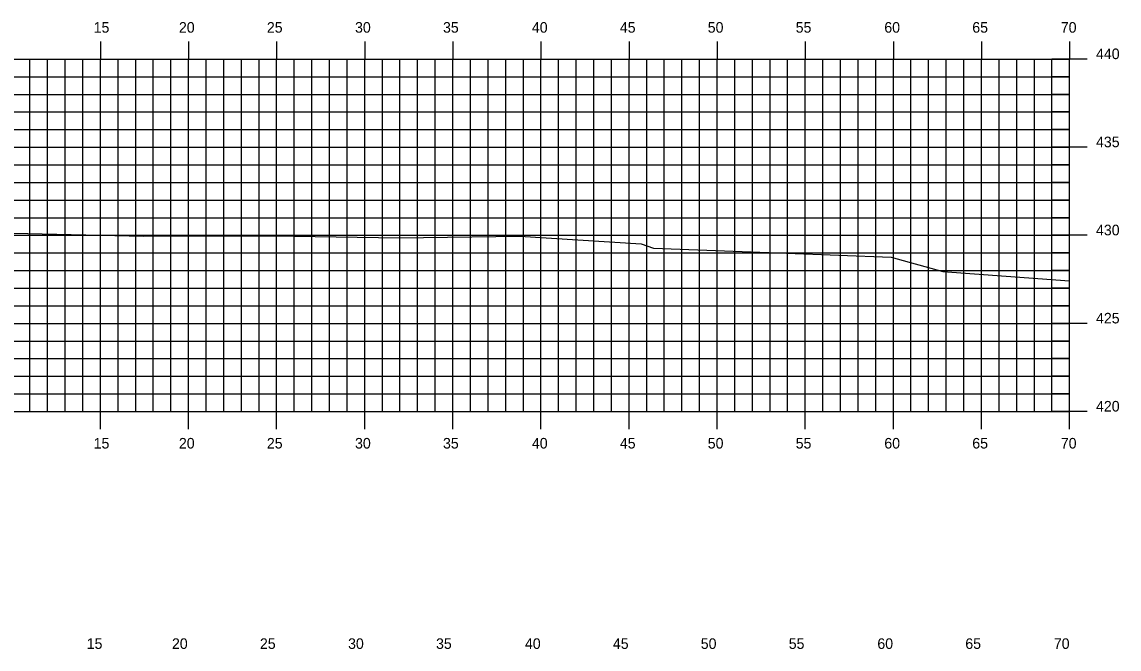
# Model space of a CAD drawing. Extents: x -161 to 764, y 111 to 210.
# Drawn here: x 165.1 to 227.4, y 153.7 to 189.3 of the extents above; entities that cross this region are included whole.
import ezdxf

# ---------------------------------------------------------------- set-up
doc = ezdxf.new("R2010")
doc.units = 0
for name, color, linetype in [('H_V ANNOTATION', 7, 'Continuous'), ('MAJOR', 7, 'Continuous'), ('MINOR', 7, 'Continuous'), ('S_Roadway_Centerline', 7, 'Continuous')]:
    doc.layers.add(name, color=color, linetype=linetype)

msp = doc.modelspace()

# ---------------------------------------------------------------- linework, layer by layer
at = {"layer": 'MAJOR'}
for p, q in [((169.563, 188.143), (169.563, 187.141)), ((174.563, 188.143), (174.563, 187.141)), ((179.563, 188.143), (179.563, 187.141)), ((184.563, 188.143), (184.563, 187.141)), ((189.563, 188.143), (189.563, 187.141)), ((194.563, 188.143), (194.563, 187.141)), ((199.563, 188.143), (199.563, 187.141)), ((204.563, 188.143), (204.563, 187.141)), ((209.563, 188.143), (209.563, 187.141)), ((214.563, 188.143), (214.563, 187.141)), ((219.563, 188.143), (219.563, 187.141)), ((224.563, 188.143), (224.563, 187.141)), ((84.563, 187.141), (224.563, 187.141)), ((84.563, 187.141), (224.563, 187.141)), ((169.563, 167.141), (169.563, 187.141)), ((174.563, 167.141), (174.563, 187.141)), ((179.563, 167.141), (179.563, 187.141)), ((184.563, 167.141), (184.563, 187.141)), ((189.563, 167.141), (189.563, 187.141)), ((194.563, 167.141), (194.563, 187.141)), ((199.563, 167.141), (199.563, 187.141)), ((204.563, 167.141), (204.563, 187.141)), ((209.563, 167.141), (209.563, 187.141)), ((214.563, 167.141), (214.563, 187.141)), ((219.563, 167.141), (219.563, 187.141)), ((225.565, 187.141), (223.561, 187.141)), ((224.563, 167.141), (224.563, 187.141)), ((224.563, 167.141), (224.563, 187.141)), ((84.563, 182.141), (224.563, 182.141)), ((225.565, 182.141), (223.561, 182.141)), ((84.563, 177.141), (224.563, 177.141)), ((225.565, 177.141), (223.561, 177.141)), ((84.563, 172.141), (224.563, 172.141)), ((225.565, 172.141), (223.561, 172.141)), ((84.563, 167.141), (224.563, 167.141)), ((84.563, 167.141), (224.563, 167.141)), ((169.563, 166.139), (169.563, 167.141)), ((174.563, 166.139), (174.563, 167.141)), ((179.563, 166.139), (179.563, 167.141)), ((184.563, 166.139), (184.563, 167.141)), ((189.563, 166.139), (189.563, 167.141)), ((194.563, 166.139), (194.563, 167.141)), ((199.563, 166.139), (199.563, 167.141)), ((204.563, 166.139), (204.563, 167.141)), ((209.563, 166.139), (209.563, 167.141)), ((214.563, 166.139), (214.563, 167.141)), ((219.563, 166.139), (219.563, 167.141)), ((225.565, 167.141), (223.561, 167.141)), ((224.563, 166.139), (224.563, 167.141))]:
    msp.add_line(p, q, dxfattribs=at)
at = {"layer": 'MINOR'}
for p, q in [((165.563, 167.141), (165.563, 187.141)), ((166.563, 167.141), (166.563, 187.141)), ((167.563, 167.141), (167.563, 187.141)), ((168.563, 167.141), (168.563, 187.141)), ((170.563, 167.141), (170.563, 187.141)), ((171.563, 167.141), (171.563, 187.141)), ((172.563, 167.141), (172.563, 187.141)), ((173.563, 167.141), (173.563, 187.141)), ((175.563, 167.141), (175.563, 187.141)), ((176.563, 167.141), (176.563, 187.141)), ((177.563, 167.141), (177.563, 187.141)), ((178.563, 167.141), (178.563, 187.141)), ((180.563, 167.141), (180.563, 187.141)), ((181.563, 167.141), (181.563, 187.141)), ((182.563, 167.141), (182.563, 187.141)), ((183.563, 167.141), (183.563, 187.141)), ((185.563, 167.141), (185.563, 187.141)), ((186.563, 167.141), (186.563, 187.141)), ((187.563, 167.141), (187.563, 187.141)), ((188.563, 167.141), (188.563, 187.141)), ((190.563, 167.141), (190.563, 187.141)), ((191.563, 167.141), (191.563, 187.141)), ((192.563, 167.141), (192.563, 187.141)), ((193.563, 167.141), (193.563, 187.141)), ((195.563, 167.141), (195.563, 187.141)), ((196.563, 167.141), (196.563, 187.141)), ((197.563, 167.141), (197.563, 187.141)), ((198.563, 167.141), (198.563, 187.141)), ((200.563, 167.141), (200.563, 187.141)), ((201.563, 167.141), (201.563, 187.141)), ((202.563, 167.141), (202.563, 187.141)), ((203.563, 167.141), (203.563, 187.141)), ((205.563, 167.141), (205.563, 187.141)), ((206.563, 167.141), (206.563, 187.141)), ((207.563, 167.141), (207.563, 187.141)), ((208.563, 167.141), (208.563, 187.141)), ((210.563, 167.141), (210.563, 187.141)), ((211.563, 167.141), (211.563, 187.141)), ((212.563, 167.141), (212.563, 187.141)), ((213.563, 167.141), (213.563, 187.141)), ((215.563, 167.141), (215.563, 187.141)), ((216.563, 167.141), (216.563, 187.141)), ((217.563, 167.141), (217.563, 187.141)), ((218.563, 167.141), (218.563, 187.141)), ((220.563, 167.141), (220.563, 187.141)), ((221.563, 167.141), (221.563, 187.141)), ((222.563, 167.141), (222.563, 187.141)), ((223.563, 167.141), (223.563, 187.141)), ((84.563, 186.141), (224.563, 186.141)), ((224.563, 186.141), (223.561, 186.141)), ((84.563, 185.141), (224.563, 185.141)), ((224.563, 185.141), (223.561, 185.141)), ((84.563, 184.141), (224.563, 184.141)), ((224.563, 184.141), (223.561, 184.141)), ((84.563, 183.141), (224.563, 183.141)), ((224.563, 183.141), (223.561, 183.141)), ((84.563, 181.141), (224.563, 181.141)), ((224.563, 181.141), (223.561, 181.141)), ((84.563, 180.141), (224.563, 180.141)), ((224.563, 180.141), (223.561, 180.141)), ((84.563, 179.141), (224.563, 179.141)), ((224.563, 179.141), (223.561, 179.141)), ((84.563, 178.141), (224.563, 178.141)), ((224.563, 178.141), (223.561, 178.141)), ((84.563, 176.141), (224.563, 176.141)), ((224.563, 176.141), (223.561, 176.141)), ((84.563, 175.141), (224.563, 175.141)), ((224.563, 175.141), (223.561, 175.141)), ((84.563, 174.141), (224.563, 174.141)), ((224.563, 174.141), (223.561, 174.141)), ((84.563, 173.141), (224.563, 173.141)), ((224.563, 173.141), (223.561, 173.141)), ((84.563, 171.141), (224.563, 171.141)), ((224.563, 171.141), (223.561, 171.141)), ((84.563, 170.141), (224.563, 170.141)), ((224.563, 170.141), (223.561, 170.141)), ((84.563, 169.141), (224.563, 169.141)), ((224.563, 169.141), (223.561, 169.141)), ((84.563, 168.141), (224.563, 168.141)), ((224.563, 168.141), (223.561, 168.141))]:
    msp.add_line(p, q, dxfattribs=at)
at = {"layer": 'S_Roadway_Centerline'}
msp.add_lwpolyline([(84.563, 173.937), (86.565, 173.962), (104.807, 174.158), (105.264, 174.178), (106.296, 174.117), (107.265, 173.972), (107.828, 174.003), (110.477, 174.125), (125.033, 175.141), (130.13, 175.365), (150.707, 176.49), (164.616, 177.272), (172.022, 177.096), (179.352, 177.108), (186.535, 177.007), (193.367, 177.096), (200.259, 176.65), (200.943, 176.413), (208.506, 176.123), (214.429, 175.907), (217.362, 175.08), (224.563, 174.564)], dxfattribs=at)

# ---------------------------------------------------------------- texts
at = {"layer": 'H_V ANNOTATION'}
for s, p in [('15', (169.18, 188.641)), ('20', (174.017, 188.641)), ('25', (179.009, 188.641)), ('30', (184.012, 188.641)), ('35', (189.004, 188.641)), ('40', (194.049, 188.641)), ('45', (199.041, 188.641)), ('50', (204.028, 188.641)), ('55', (209.02, 188.641)), ('60', (214.049, 188.641)), ('65', (219.041, 188.641)), ('70', (224.065, 188.641)), ('440', (226.063, 187.141)), ('435', (226.063, 182.141)), ('430', (226.063, 177.141)), ('425', (226.063, 172.141)), ('420', (226.063, 167.141)), ('15', (169.18, 165.041)), ('20', (174.017, 165.041)), ('25', (179.009, 165.041)), ('30', (184.012, 165.041)), ('35', (189.004, 165.041)), ('40', (194.049, 165.041)), ('45', (199.041, 165.041)), ('50', (204.028, 165.041)), ('55', (209.02, 165.041)), ('60', (214.049, 165.041)), ('65', (219.041, 165.041)), ('70', (224.065, 165.041)), ('15', (168.785, 153.669)), ('20', (173.622, 153.669)), ('25', (178.614, 153.669)), ('30', (183.616, 153.669)), ('35', (188.608, 153.669)), ('40', (193.654, 153.669)), ('45', (198.646, 153.669)), ('50', (203.632, 153.669)), ('55', (208.624, 153.669)), ('60', (213.654, 153.669)), ('65', (218.646, 153.669)), ('70', (223.67, 153.669))]:
    msp.add_text(s, height=0.6, rotation=360, dxfattribs=at).set_placement(p)

doc.saveas('drawing.dxf')
